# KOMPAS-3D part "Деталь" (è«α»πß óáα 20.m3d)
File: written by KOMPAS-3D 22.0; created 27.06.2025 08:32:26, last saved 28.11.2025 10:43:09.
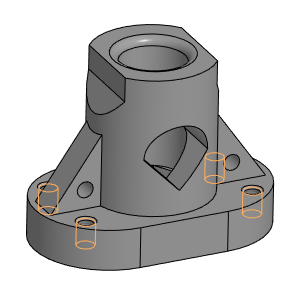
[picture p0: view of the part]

Document properties: Автор: alymovy@yandex.ru; Организация: HP; Полное имя файла: КорпусВариант 20.cdw

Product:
- Part/product: Деталь
    Материал: Полиамид П-12Б-20 ТУ 6-05-898-73 (density 1020 kg/m3)
    Масса: 0.503262
    Форматы листов документа: A3

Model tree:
1. Эскиз:1
2. Элемент выдавливания:1
     Расстояние 1 = 25
3. Эскиз:2  (with: Элемент выдавливания:1)
4. Элемент выдавливания:2
     Расстояние 1 = 85
5. Эскиз:3  (with: Элемент выдавливания:1, Элемент выдавливания:2)
6. Ребро жесткости:1
     Толщина стенки 1 = 20; Толщина стенки 2 = 1
7. Зеркальный массив:1
8. Экземпляр ( 1 )
9. Экземпляр ( 2 )  (with: Ребро жесткости:1)
10. Эскиз:4  (with: Элемент выдавливания:2)
11. Элемент выдавливания:3
     Расстояние 1 = 45
12. Эскиз:5  (with: Элемент выдавливания:2)
13. Элемент выдавливания:4
     Расстояние 2 = 80
14. Скругление:1  (with: Элемент выдавливания:4)
     Радиус = 5
15. Эскиз:6  (with: Элемент выдавливания:4)
16. Элемент выдавливания:5
     Расстояние 2 = 30
17. Эскиз:7  (with: Ребро жесткости:1)
18. Элемент выдавливания:6
     Расстояние 1 = 35
19. Эскиз:8  (with: Элемент выдавливания:1)
20. Отверстие:1  (with: Элемент выдавливания:1, Ребро жесткости:1)  (labels: M11)
     Глубина выреза = 20; Диаметр отверстия = 9.3762; Угол конуса дна = 118; Расстояние 1 = 20.2513; Расстояние 2 = 119.749; Диаметр зенковки = 12.5762; Глубина зенковки = 1.6; Угол зенковки = 90
21. M11  (with: Отверстие:1)  (labels: cil0_24705-2004 coarse)
     Длина резьбы = 15; Шаг резьбы = 1.5; Номинальный диаметр резьбы = 11
22. Зеркальный массив:2  (with: Экземпляр ( 1 ), Экземпляр ( 2 ), Отверстие:1)
23. Зеркальный массив:3  (with: Экземпляр ( 1 ), Экземпляр ( 2 ), Зеркальный массив:2, Отверстие:1)
24. Экземпляр ( 2 )  (with: Отверстие:1)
